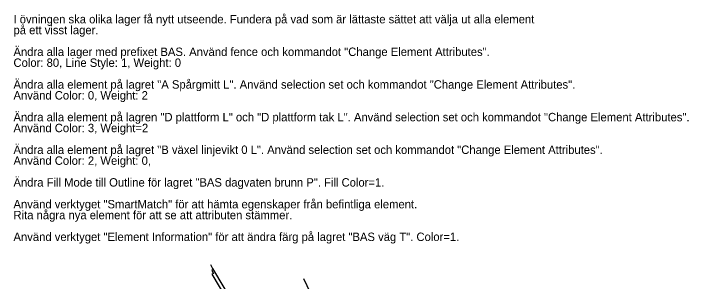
# Model space of a CAD drawing. Extents: x 1596643 to 1597288, y 13057194 to 13057957.
# Drawn here: x 1596643 to 1597288, y 13057701 to 13057957 of the extents above; entities that cross this region are included whole.
import ezdxf

# ---------------------------------------------------------------- set-up
doc = ezdxf.new("R2010")
doc.units = 0
for name, color, linetype in [('BAS byggnad anläggning L', 7, 'Continuous'), ('BAS fastighetsgräns samfällighet L', 7, 'Continuous'), ('Instruktioner', 7, 'Continuous')]:
    doc.layers.add(name, color=color, linetype=linetype)

msp = doc.modelspace()

# ---------------------------------------------------------------- linework, layer by layer
at = {"layer": 'BAS byggnad anläggning L'}
for points in [[(1596831.41, 13057716.96), (1596833.52, 13057713.23), (1596898.19, 13057604.41), (1596899.71, 13057604.86)], [(1596834.08, 13057712.23), (1596832.69, 13057711.29), (1596834.41, 13057708.47), (1596832.82, 13057707.63), (1596890.17, 13057611.25), (1596868.67, 13057598.44)]]:
    msp.add_lwpolyline(points, dxfattribs=at)
at = {"layer": 'BAS fastighetsgräns samfällighet L'}
msp.add_lwpolyline([(1596920.39, 13057703.46), (1596969.69, 13057599.79)], dxfattribs=at)

# ---------------------------------------------------------------- texts
at = {"layer": 'Instruktioner'}
for s, height, p in [('I övningen ska olika lager få nytt utseende. Fundera på vad som är lättaste sättet att välja ut alla element', 8.02981, (1596643.41, 13057947.23)), ('på ett visst lager.', 8.0298, (1596643.41, 13057936.84)), ('Ändra alla lager med prefixet BAS. Använd fence och kommandot "Change Element Attributes".', 8.0298, (1596643.41, 13057916.06)), ('Color: 80, Line Style: 1, Weight: 0', 8.0298, (1596643.41, 13057905.67)), ('Ändra alla element på lagret "A Spårgmitt L". Använd selection set och kommandot "Change Element Attributes".', 8.02981, (1596643.41, 13057884.88)), ('Använd Color: 0, Weight: 2', 8.0298, (1596643.41, 13057874.49)), ('Ändra alla element på lagren "D plattform L" och "D plattform tak L". Använd selection set och kommandot "Change Element Attributes".', 8.02981, (1596643.41, 13057853.7)), ('Använd Color: 3, Weight=2', 8.0298, (1596643.41, 13057843.31)), ('Ändra alla element på lagret "B växel linjevikt 0 L". Använd selection set och kommandot "Change Element Attributes".', 8.02981, (1596643.41, 13057822.53)), ('Använd Color: 2, Weight: 0, ', 8.0298, (1596643.41, 13057812.14)), ('Ändra Fill Mode till Outline för lagret "BAS dagvaten brunn P". Fill Color=1.', 8.0298, (1596643.41, 13057791.35)), ('Använd verktyget "SmartMatch" för att hämta egenskaper från befintliga element.', 8.0298, (1596643.41, 13057770.57)), ('Rita några nya element för att se att attributen stämmer.', 8.0298, (1596643.41, 13057760.17)), ('Använd verktyget "Element Information" för att ändra färg på lagret "BAS väg T". Color=1.', 8.0298, (1596643.41, 13057739.39))]:
    msp.add_text(s, height=height, dxfattribs=at).set_placement(p)

doc.saveas('drawing.dxf')
